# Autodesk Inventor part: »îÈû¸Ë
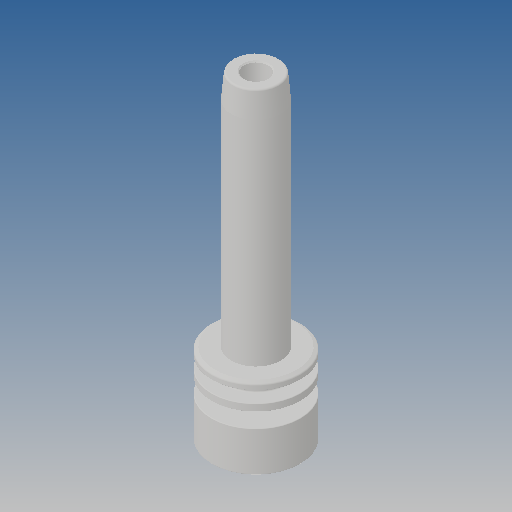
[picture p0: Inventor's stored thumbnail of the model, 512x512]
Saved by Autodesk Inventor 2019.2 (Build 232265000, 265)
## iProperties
Created: 2013-09
Part Number: »îÈû¸Ë
Material: Ogólny
Document SubType Name: Modeling
Designer: CADENGINEERING4
Density: 1 g/cm^3
Appearance: Domyślna
Author: CADENGINEERING4
Revision Number: ÈÎºÎ
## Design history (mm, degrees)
feature "µ¹½Ç2"
node "Bryła1"
